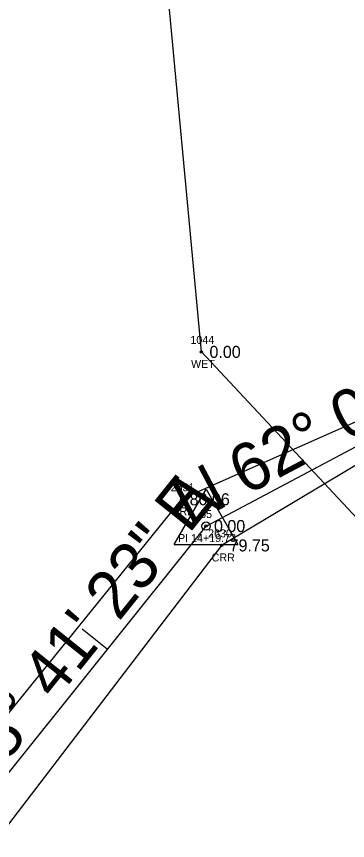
# Model space of a CAD drawing. Extents: x 2139392 to 2143384, y 505395 to 510520.
# Drawn here: x 2140530.7 to 2140572, y 506739.4 to 506842.3 of the extents above; entities that cross this region are included whole.
import ezdxf

# ---------------------------------------------------------------- set-up
doc = ezdxf.new("R2010")
doc.units = 0
for name, color, linetype in [('RD_EV_EX_Wetlands', 7, 'Continuous'), ('RD_EX_H2O', 7, 'Continuous'), ('RD_EX_H2O_txCode', 7, 'Continuous'), ('RD_EX_H2O_WetLd_txCode', 7, 'Continuous'), ('RD_EX_TX_H2O_ELEV', 7, 'Continuous'), ('RD_EX_TX_H2O_WetLd_ELEV', 7, 'Continuous'), ('RD_HC_Cl', 7, 'Continuous'), ('RD_HC_Data', 7, 'Continuous'), ('RD_HC_Data_Tic', 7, 'Continuous'), ('RD_HC_Survey_ELEV', 7, 'Continuous'), ('RD_HC_txCode', 7, 'Continuous'), ('RD_SMD_Locator', 7, 'Continuous')]:
    doc.layers.add(name, color=color, linetype=linetype)

msp = doc.modelspace()

# ---------------------------------------------------------------- linework, layer by layer
at = {"layer": 'RD_EV_EX_Wetlands'}
msp.add_lwpolyline([(2140603.94, 506746.81), (2140553.79, 506800.44), (2140548.97, 506852.16), (2140544.79, 506916.87), (2140531.27, 506972.76), (2140535.71, 507012.16)], dxfattribs=at)
at = {"layer": 'RD_EX_H2O'}
for points in [[(2140595.86, 506808.79), (2140590.86, 506807.57), (2140591.7, 506801.01), (2140576.01, 506792.99), (2140551.31, 506782.03), (2140521.97, 506745.85), (2140473.31, 506728.17), (2140432.02, 506696.18), (2140374.62, 506691.81), (2140362.76, 506675.27), (2140331.34, 506688.09), (2140289.89, 506693.34), (2140243.27, 506706.89), (2140157.85, 506698.32), (2140125.33, 506735.71)], [(2140597.11, 506796.14), (2140592.29, 506797.04), (2140578.11, 506789.28), (2140556.31, 506776.27), (2140527.45, 506738.61), (2140475.88, 506720.16), (2140433.27, 506689.29), (2140378.98, 506685.41), (2140363.61, 506658.12), (2140329.18, 506677.67), (2140287.66, 506681.81), (2140243.93, 506698.42), (2140156.17, 506695.49), (2140124.7, 506729.24)]]:
    msp.add_lwpolyline(points, dxfattribs=at)
at = {"layer": 'RD_HC_Cl'}
for p, q in [((2140554.36, 506778.69), (2140600.46, 506803.15)), ((2140525.23, 506742.33), (2140554.36, 506778.69))]:
    msp.add_line(p, q, dxfattribs=at)
at = {"layer": 'RD_HC_Data'}
for p, q in [((2140550.39, 506776.4), (2140554.36, 506783.28)), ((2140554.36, 506783.28), (2140558.33, 506776.4)), ((2140550.39, 506776.4), (2140558.33, 506776.4))]:
    msp.add_line(p, q, dxfattribs=at)
msp.add_circle((2140554.36, 506778.69), 0.529, dxfattribs=at)
at = {"layer": 'RD_HC_Data_Tic'}
msp.add_line((2140542.02, 506763.29), (2140538.9, 506765.79), dxfattribs=at)
at = {"layer": 'RD_SMD_Locator'}
for centre in [(2140553.79, 506800.44), (2140551.31, 506782.03), (2140554.36, 506778.69), (2140556.31, 506776.27)]:
    msp.add_circle(centre, 0.15, dxfattribs=at)

# ---------------------------------------------------------------- texts
at = {"layer": 'RD_EX_H2O_txCode'}
for s, p in [('2631', (2140549.94, 506783.03)), ('CRL', (2140550.08, 506780.03)), ('2630', (2140554.62, 506777.27)), ('CRR', (2140555.06, 506774.27))]:
    msp.add_text(s, height=1, dxfattribs=at).set_placement(p)
at = {"layer": 'RD_EX_H2O_WetLd_txCode'}
for s, p in [('1044', (2140552.41, 506801.44)), ('WET', (2140552.49, 506798.44))]:
    msp.add_text(s, height=1, dxfattribs=at).set_placement(p)
at = {"layer": 'RD_EX_TX_H2O_ELEV'}
for s, p in [('80.06', (2140552.31, 506781.28)), ('79.75', (2140557.31, 506775.52))]:
    msp.add_text(s, height=1.5, dxfattribs=at).set_placement(p)
at = {"layer": 'RD_EX_TX_H2O_WetLd_ELEV'}
msp.add_text('0.00', height=1.5, dxfattribs=at).set_placement((2140554.79, 506799.69))
at = {"layer": 'RD_HC_Data'}
for s, rotation, p in [('N 62%%d 03\' 32" E', 27.941, (2140552.22, 506778.69)), ('N 38%%d 41\' 23" E', 51.3102, (2140521.53, 506739.3))]:
    msp.add_text(s, height=6, rotation=rotation, dxfattribs=at).set_placement(p)
at = {"layer": 'RD_HC_Survey_ELEV'}
msp.add_text('0.00', height=1.5, dxfattribs=at).set_placement((2140555.36, 506777.94))
at = {"layer": 'RD_HC_txCode'}
for s, p in [('55', (2140553.62, 506779.69)), ('PI 14+19.73', (2140550.86, 506776.69))]:
    msp.add_text(s, height=1, dxfattribs=at).set_placement(p)

doc.saveas('drawing.dxf')
